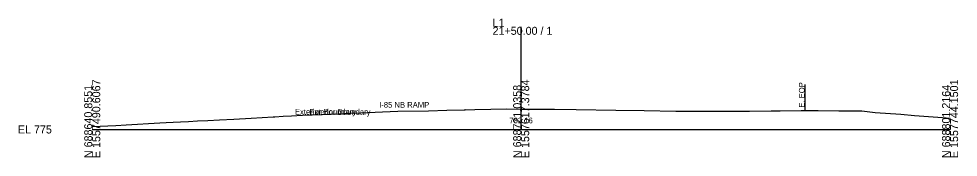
# Model space of a CAD drawing. Extents: x -26 to 2603, y -3010 to 9589.
# Drawn here: x -25.7 to 302.8, y 4990.3 to 5038.7 of the extents above; entities that cross this region are included whole.
import ezdxf

# ---------------------------------------------------------------- set-up
doc = ezdxf.new("R2010")
doc.units = 0
for name, color, linetype in [('Default', 7, 'Continuous'), ('Exist Cross Section Cell', 7, 'Continuous'), ('Exist XS Center Line Elevation Label', 7, 'Continuous'), ('Exist XS Ground Line', 7, 'Continuous'), ('Prop XS Label Text', 7, 'Continuous'), ('Prop XS Side Slope Text', 7, 'Continuous')]:
    doc.layers.add(name, color=color, linetype=linetype)

msp = doc.modelspace()

# ---------------------------------------------------------------- linework, layer by layer
at = {"layer": 'Exist Cross Section Cell'}
for p, q in [((150, 5000), (150, 5035.91)), ((0, 5000), (150, 5000)), ((150, 5000), (300, 5000))]:
    msp.add_line(p, q, dxfattribs=at)
at = {"layer": 'Exist XS Ground Line'}
msp.add_lwpolyline([(0, 5001.06), (8.24, 5001.4), (11.9, 5001.6), (23.58, 5002.35), (25.87, 5002.4), (28.26, 5002.52), (30.83, 5002.66), (33.64, 5002.81), (36.79, 5002.97), (40.37, 5003.17), (44.53, 5003.39), (49.5, 5003.66), (55.59, 5004), (63.29, 5004.42), (63.81, 5004.45), (66.81, 5004.61), (69.68, 5004.77), (73.52, 5004.97), (80.46, 5005.24), (86, 5005.5), (90.24, 5005.7), (93.55, 5005.85), (106.9, 5006.42), (117.57, 5006.57), (124.03, 5006.76), (130.24, 5006.92), (130.39, 5007.12), (130.56, 5006.93), (133.85, 5007.01), (144.95, 5007.17), (150, 5007.15), (150.57, 5007.14), (161.66, 5007.13), (169.23, 5006.98), (183.16, 5006.73), (193.02, 5006.61), (204.03, 5006.46), (206.11, 5006.45), (213.91, 5006.44), (215.59, 5006.43), (219.12, 5006.44), (225.64, 5006.41), (229.83, 5006.45), (237.41, 5006.48), (240.57, 5006.52), (247.95, 5006.67), (249.22, 5006.69), (253.84, 5006.62), (261.11, 5006.58), (264.08, 5006.53), (265.51, 5006.52), (269.16, 5006.5), (273.8, 5005.97), (282.82, 5005.33), (287.51, 5004.86), (297.35, 5004.16), (300, 5003.96)], dxfattribs=at)
at = {"layer": 'Prop XS Label Text'}
msp.add_line((249.22, 5015.69), (249.22, 5006.69), dxfattribs=at)

# ---------------------------------------------------------------- texts
at = {"layer": 'Default'}
for s, height, p in [('Exterior Boundary', 2, (70.89, 5005.22)), ('Exterior Boundary', 2, (75.89, 5005.12)), ('-', 0.0001, (0, 5000))]:
    msp.add_text(s, height=height, dxfattribs=at).set_placement(p)
at = {"layer": 'Exist Cross Section Cell'}
for s, p in [('L1', (140, 5035.91)), ('21+50.00 / 1', (140, 5033.11)), ('EL 775', (-26, 4998.6))]:
    msp.add_text(s, height=2.8, dxfattribs=at).set_placement(p)
for s, p in [('E 1557490.6067', (2.8, 4990)), ('E 1557617.3784', (152.8, 4990)), ('E 1557744.1501', (302.8, 4990)), ('N 688640.8551', (0, 4990)), ('N 688721.0358', (150, 4990)), ('N 688801.2164', (300, 4990))]:
    msp.add_text(s, height=2.8, rotation=90, dxfattribs=at).set_placement(p)
at = {"layer": 'Exist XS Center Line Elevation Label'}
msp.add_text('782.16', height=2, dxfattribs=at).set_placement((145.87, 5002.16))
at = {"layer": 'Prop XS Label Text'}
msp.add_text('E. EOP', height=2, rotation=90, dxfattribs=at).set_placement((249.12, 5007.61))
at = {"layer": 'Prop XS Side Slope Text'}
msp.add_text('I-85 NB RAMP', height=2, rotation=0.014, dxfattribs=at).set_placement((100.33, 5007.62))

doc.saveas('drawing.dxf')
